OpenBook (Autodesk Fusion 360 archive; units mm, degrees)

design "Proiect - TEMA"
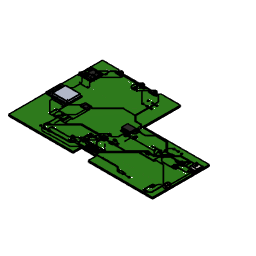
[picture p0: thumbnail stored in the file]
sketch "Outline" plane through (0, 0, 0) normal (0, 0, 1) x axis (1, 0, 0)
  line L1 (76.2, 0) -> (0, 0)
  line L2 (76.2, 9.9999) -> (76.2, 0)
  line L3 (94.3991, 10) -> (76.2, 9.9999)
  line L4 (94.3991, 0) -> (94.3991, 10)
  line L5 (170.1546, 0) -> (94.3991, 0)
  line L6 (170.1546, 67.2008) -> (170.1546, 0)
  line L7 (92.1205, 66.9752) -> (170.1546, 67.2008)
  line L8 (92.202, 110.9726) -> (92.1205, 66.9752)
  line L9 (68.58, 110.9726) -> (92.202, 110.9726)
  line L10 (68.58, 109.12) -> (68.58, 110.9726)
  line L11 (19.7274, 109.12) -> (68.58, 109.12)
  line L12 (19.7274, 110.9726) -> (19.7274, 109.12)
  line L13 (0, 110.9726) -> (19.7274, 110.9726)
  line L14 (0, 61.6) -> (0, 110.9726)
  line L15 (6.5, 61.6) -> (0, 61.6)
  line L16 (6.5, 43.3) -> (6.5, 61.6)
  line L17 (0, 43.3) -> (6.5, 43.3)
  line L18 (0, 0) -> (0, 43.3)
canvas "Canvas1" bodies "Board"
canvas "Canvas2" bodies "Board"
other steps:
base_feature "Base Feature1"
base_feature "Base Feature1"
base_feature "Base Feature1"
base_feature "Base Feature1"
base_feature "Base Feature1"
base_feature "Base Feature1"
base_feature "Base Feature1"
base_feature "Base Feature1"
base_feature "Base Feature1"
base_feature "Base Feature1"
base_feature "Base Feature1"
base_feature "Base Feature1"
base_feature "Base Feature1"
base_feature "Base Feature1"
base_feature "Base Feature1"
base_feature "Base Feature1"
base_feature "Base Feature1"
base_feature "Base Feature1"
base_feature "Base Feature1"
base_feature "Base Feature1"
base_feature "Base Feature1"
base_feature "Base Feature1"
base_feature "Base Feature1"
base_feature "Base Feature1"
base_feature "Base Feature1"
base_feature "Base Feature1"
base_feature "Base Feature1"
base_feature "Base Feature1"
base_feature "Base Feature1"
base_feature "Base Feature1"
base_feature "Base Feature1"
base_feature "Base Feature1"
base_feature "Base Feature1"
base_feature "Base Feature1"
base_feature "Base Feature1"
base_feature "Base Feature1"
base_feature "Base Feature1"
base_feature "Base Feature1"
base_feature "Base Feature1"
extrude "Extrude1" sketch "Outline" blind 1.6 bodies "Board"
base_feature "Base Feature1"
pcbextrude "PCBExtrude1"
base_feature "Base Feature1"
base_feature "Base Feature1"
base_feature "Base Feature1"
base_feature "Base Feature1"
base_feature "Base Feature1"
base_feature "Base Feature1"
base_feature "Base Feature1"
base_feature "Base Feature1"
base_feature "Base Feature1"
base_feature "Base Feature1"
base_feature "Base Feature1"
base_feature "Base Feature1"
base_feature "Base Feature1"
base_feature "Base Feature1"
base_feature "Base Feature1"
base_feature "Base Feature1"
base_feature "Base Feature1"
base_feature "Base Feature1"
base_feature "Base Feature1"
base_feature "Base Feature1"
base_feature "Base Feature1"
base_feature "Base Feature1"
base_feature "Base Feature1"
base_feature "Base Feature1"
base_feature "Base Feature1"
base_feature "Base Feature1"
base_feature "Base Feature1"
base_feature "Base Feature1"
base_feature "Base Feature1"
base_feature "Base Feature1"
base_feature "Base Feature1"
base_feature "Base Feature1"
base_feature "Base Feature1"
base_feature "Base Feature1"
base_feature "Base Feature1"
base_feature "Base Feature1"
base_feature "Base Feature1"
base_feature "Base Feature1"
base_feature "Base Feature1"
base_feature "Base Feature1"
base_feature "Base Feature1"
base_feature "Base Feature1"
base_feature "Base Feature1"
base_feature "Base Feature1"
base_feature "Base Feature1"
base_feature "Base Feature1"
pcbextrude "PCBExtrude1"
pcbextrude "PCBExtrude1"
base_feature "Base Feature1"
pcbextrude "PCBExtrude1"
pcbextrude "PCBExtrude1"
pcbhole "PCBHole2"
pcbhole "PCBHole2"
pcbextrude "PCBExtrude2" bodies "CopperHoles"
pcbhole "PCBHole2"
create_component "CreateComponent1"
create_component "CreateComponent2"
create_component "CreateComponent3"
create_component "CreateComponent4"
create_component "CreateComponent5"
create_component "CreateComponent6"
create_component "CreateComponent1"
create_component "CreateComponent1"
as_built_joint "As-built1"
create_component "CreateComponent31"
create_component "CreateComponent1"
create_component "CreateComponent1"
create_component "CreateComponent2"
create_component "CreateComponent3"
create_component "CreateComponent32"
create_component "CreateComponent1"
create_component "CreateComponent33"
create_component "CreateComponent1"
create_component "CreateComponent34"
create_component "CreateComponent1"
create_component "CreateComponent35"
create_component "CreateComponent1"
create_component "CreateComponent36"
create_component "CreateComponent1"
create_component "CreateComponent37"
create_component "CreateComponent1"
create_component "CreateComponent38"
create_component "CreateComponent1"
create_component "CreateComponent1"
create_component "CreateComponent2"
create_component "CreateComponent3"
create_component "CreateComponent39"
create_component "CreateComponent1"
create_component "CreateComponent1"
create_component "CreateComponent2"
create_component "CreateComponent3"
create_component "CreateComponent40"
create_component "CreateComponent1"
create_component "CreateComponent41"
create_component "CreateComponent1"
create_component "CreateComponent43"
create_component "CreateComponent1"
create_component "CreateComponent45"
create_component "CreateComponent1"
create_component "CreateComponent46"
create_component "CreateComponent1"
create_component "CreateComponent1"
create_component "CreateComponent2"
create_component "CreateComponent3"
create_component "CreateComponent47"
create_component "CreateComponent1"
create_component "CreateComponent1"
create_component "CreateComponent2"
create_component "CreateComponent3"
create_component "CreateComponent48"
create_component "CreateComponent1"
create_component "CreateComponent1"
create_component "CreateComponent2"
create_component "CreateComponent3"
create_component "CreateComponent49"
create_component "CreateComponent1"
create_component "CreateComponent50"
create_component "CreateComponent1"
create_component "CreateComponent51"
create_component "CreateComponent1"
create_component "CreateComponent52"
create_component "CreateComponent1"
create_component "CreateComponent53"
create_component "CreateComponent1"
create_component "CreateComponent1"
create_component "CreateComponent2"
create_component "CreateComponent3"
create_component "CreateComponent54"
create_component "CreateComponent1"
create_component "CreateComponent1"
create_component "CreateComponent2"
create_component "CreateComponent3"
create_component "CreateComponent55"
create_component "CreateComponent1"
create_component "CreateComponent56"
create_component "CreateComponent57"
create_component "CreateComponent1"
create_component "CreateComponent58"
create_component "CreateComponent1"
create_component "CreateComponent1"
create_component "CreateComponent2"
create_component "CreateComponent3"
create_component "CreateComponent59"
create_component "CreateComponent1"
create_component "CreateComponent60"
create_component "CreateComponent1"
create_component "CreateComponent61"
create_component "CreateComponent1"
create_component "CreateComponent1"
named bodies: "Board", "CopperHoles"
